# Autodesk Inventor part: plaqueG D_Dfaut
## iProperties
Created: 2007-07
Part Number: plaqueG D_Dfaut
Document SubType Name: Modeling
Designer: EF
Density: 1 g/cm^3
Author: EF
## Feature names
1. Base1
